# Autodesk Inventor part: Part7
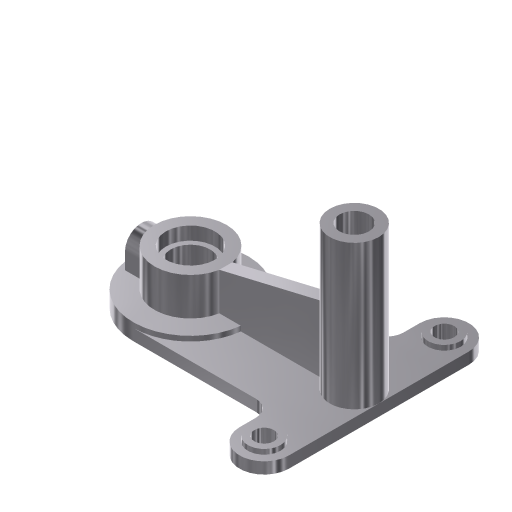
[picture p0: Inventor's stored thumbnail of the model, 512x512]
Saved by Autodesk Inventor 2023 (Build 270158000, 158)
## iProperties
Created: 2001-12
Part Number: Part7
Document SubType Name: Modeling
Density: 1 g/cm^3
Material: Generic
Appearance: Metal-AL-6061 (Polished)
Control State: 0
Master: False
Checked Out: False
Shininess: 77.0
Length Units: 11269
Angle Units: 11279
Time Units: 11290
Mass Units: 11283
Length Display Precision: 3
Angle Display Precision: 2
Density: 0.0
Volumn: 0.0
Area: 0.0
PropertySet Name: Model Information
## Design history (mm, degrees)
sketch "Sketch1"
  geometry: L1 (46.121, -53.4)-(46.121, 56.6); L2 (16.121, 56.6)-(16.121, 36.6); L3 (16.121, 36.6)-(-68.879, 36.6); L4 (-68.879, -33.4)-(16.121, -33.4); L5 (16.121, -33.4)-(16.121, -53.4); A1 r 15 centre (31.121, 56.6) between (46.121, 56.6) and (16.121, 56.6); A2 r 35 centre (-68.879, 1.6) between (-68.879, 36.6) and (-68.879, -33.4); A3 r 15 centre (31.121, -53.4) between (16.121, -53.4) and (46.121, -53.4)
  constraints: 10 end point, 6 point on circle, 5 tangent, 3 centre point, 3 parallel, 2 equal length, 1 equal radius, 1 perpendicular, 1 vertical
  dimensions: "d0" = 15 radius of A1; "d1" = 110 distance of L1.start L1.end; "d2" = 100 horizontal distance of A3.centre A2.centre; "d3" = 35 radius of A2
extrude "Extrusion1" new body sketch "Sketch1" distance "d4" = 7; taper "d5" = 0 deg
sketch "Sketch2"
  geometry: C1 r 10 at (31.121, 56.6); C2 r 10 at (31.121, -53.4); C3 r 35 at (-68.879, 1.6); A1 r 35 centre (-68.879, 1.6) between (-68.879, 36.6) and (-68.879, -33.4) reference; A2 r 15 centre (31.121, 56.6) between (46.121, 56.6) and (16.121, 56.6) reference; A3 r 15 centre (31.121, -53.4) between (16.121, -53.4) and (46.121, -53.4) reference
  constraints: 3 centre point, 3 concentric, 2 equal radius
  dimensions: "d45" = 20 diameter of C1
extrude "Extrusion2" join sketch "Sketch2" distance "d6" = 3; taper "d7" = 0 deg
sketch "Sketch3"
  geometry: C1 r 22 at (0, 0); 1 further point
  constraints: 1 centre point, 1 coincident
  dimensions: "d8" = 44 diameter of C1
extrude "Extrusion3" join sketch "Sketch3" distance "d9" = 23; taper "d10" = 0 deg
sketch "Sketch4"
  geometry: L1 (46.121, 56.6)-(46.121, -53.4) reference; L2 (-68.879, 36.6)-(16.121, 36.6) reference; C1 r 15 at (31.121, 1.6)
  constraints: 1 centre point
  dimensions: "d11" = 30 diameter of C1; "d12" = 15 distance from line of L1 C1.centre; "d13" = 35 distance from line of L2 C1.centre
extrude "Extrusion4" join sketch "Sketch4" distance "d14" = 88; taper "d15" = 0 deg
workplane "Work Plane1"
sketch "Sketch5"
  geometry: L1 (22, 33.1)-(85, 48); L2 (0, 7)-(35, 7) reference; L3 (85, 0)-(85, 7) reference; L4 (115, 0)-(115, 7) reference; L5 (115, 0)-(85, 0) reference
  constraints: 2 end point
  dimensions: "d17" = 26.1 distance from line of L2 L1.start; "d18" = 63 distance from line of L3 L1.start; "d19" = 30 distance from line of L4 L1.end; "d20" = 48 distance from line of L5 L1.end
feature "Rib1" sketch "Sketch5" dims "d21" = 1, "d22" = 8
workplane "Work Plane2"
workplane "Work Plane3"
sketch "Sketch7"
  geometry: L1 (10, 0)-(10, 10); L2 (-10, 10)-(-10, 0); L3 (-10, 0)-(10, 0); L4 (55, -10)-(55, -3) reference; A1 r 10 centre (0, 10) between (10, 10) and (-10, 10); 2 further points
  constraints: 6 end point, 2 point on circle, 2 tangent, 1 centre point, 1 parallel, 1 perpendicular, 1 vertical
  dimensions: "d30" = 10 radius of A1; "d34" = 55 distance from line of L4 A1.centre; "d35" = 10 distance of L1.start L1.end
extrude "Extrusion6" join sketch "Sketch7" stored distance "d36" = 88; taper "d37" = 0 deg
sketch "Sketch8"
  geometry: C1 r 10 at (0, 0) reference
hole "Hole1" sketch "Sketch8" at (0, 0) diameter "d38" = 12; stored, may be unused: countersink angle "d42" = 82 deg, drill point angle "d44" = 118 deg; dims "d39" = 6, "d40" = 4, "d41" = 2, "d43" = 8
mirror "Mirror1"
sketch "Sketch9"
  geometry: C1 r 10 at (0, 0)
  constraints: 1 centre point
hole "Hole2" sketch "Sketch9" at (0, 0) diameter "d52" = 18; stored, may be unused: drill point angle "d47" = 118 deg, countersink angle "d48" = 82 deg; dims "d46" = 6, "d49" = 2, "d50" = 4, "d51" = 8
sketch "Sketch10"
  geometry: C1 r 10 at (0, 0)
  constraints: 1 centre point
hole "Hole3" sketch "Sketch10" at (0, 0) diameter "d59" = 24; stored, may be unused: drill point angle "d54" = 118 deg, countersink angle "d55" = 82 deg; dims "d53" = 6, "d56" = 8, "d57" = 30, "d58" = 8
sketch "Sketch11"
  geometry: C1 r 10 at (0, 0)
  constraints: 1 centre point
hole "Hole4" sketch "Sketch11" at (0, 0) diameter "d66" = 10; stored, may be unused: drill point angle "d61" = 0 deg, countersink angle "d62" = 82 deg; dims "d60" = 6, "d63" = 2, "d64" = 4, "d65" = 8
fillet "Fillet1" dims "d67" = 10
body "Solid1"
other parameters: "d16" = -35, "d29" = -8
